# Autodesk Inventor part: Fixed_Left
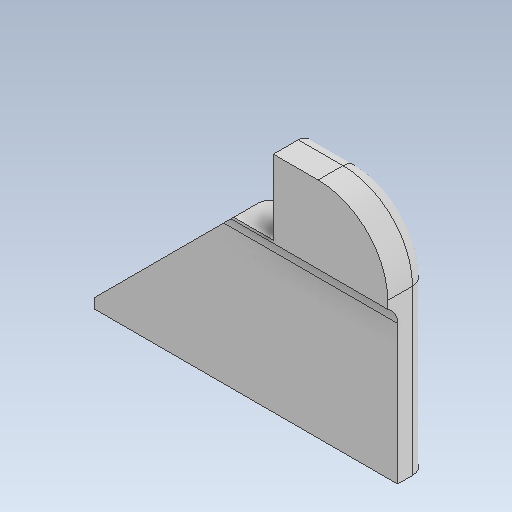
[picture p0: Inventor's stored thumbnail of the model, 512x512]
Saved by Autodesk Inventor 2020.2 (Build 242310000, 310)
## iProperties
Created: 2019-12
Part Number: Fixed_Left
Material: Generic
Document SubType Name: Modeling
Designer: Patrick Everitt
Density: 1 g/cm^3
Appearance: Default
Description: 1x6 CRS 8 Lg
Author: Patrick Everitt
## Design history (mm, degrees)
sketch "Sketch1"
  geometry: L1 (25.4, -50.8)-(25.4, -3.175); L2 (25.4, -50.8)-(73.025, -50.8); L3 (25.4, -3.175)-(53.975, -3.175); L4 (98.425, -47.625)-(98.425, -152.4); L5 (25.4, -50.8)-(0, -50.8); L6 (98.425, -152.4)-(-95.25, -152.4); L7 (0, -50.8)-(-95.25, -146.05); L8 (-95.25, -146.05)-(-95.25, -152.4); A1 r 44.45 centre (53.975, -47.625) between (98.425, -47.625) and (53.975, -3.175); 2 further points
  constraints: 16 end point, 4 perpendicular, 3 horizontal, 2 point on circle, 2 point on line, 2 tangent, 1 centre point, 1 vertical
  dimensions: "d6" = 47.625 distance of L1.start L1.end; "d7" = 90 deg angle of L2 L1 (derived); "d8" = 73.025 distance of L1.end point (98.425, -3.175); "d9" = 90 deg angle of L1 L3 (derived); "d11" = 90 deg angle of L3 L4 (derived); "d14" = 25.4 horizontal distance of point (0, 0) L1.end; "d17" = 101.6 vertical distance of L6.end L5.end; "d18" = 44.45 radius of A1 (derived); "d62" = 3.175 vertical distance of point (0, 0) L1.end; "d66" = 25.4 distance of L1.start L5.end (= d14); "d67" = 135 deg angle of L5 L7; "d69" = 6.35 distance of L7.end L6.end
extrude "Extrusion1" new body sketch "Sketch1" distance "d25" = 25.4; taper "d26" = 0 deg
sketch "Sketch2"
  geometry: L1 (0, 0)-(-25.4, 0) reference; L2 (-19.05, 0)-(-19.05, 88.9); L3 (-25.4, 101.6)-(-25.4, 0) reference; L4 (-31.75, 101.6)-(-44.45, 101.6); L5 (-44.45, 101.6)-(-44.45, 0); L6 (-44.45, 0)-(-19.05, 0); A1 r 12.7 centre (-31.75, 88.9) between (-19.05, 88.9) and (-31.75, 101.6); 4 further points
  constraints: 8 end point, 2 perpendicular, 2 point on circle, 2 point on line, 2 tangent, 1 centre point, 1 parallel
  dimensions: "d37" = 25.4 distance of point (-19.05, 101.6) L4.end; "d39" = 12.7 radius of A1 (derived); "d40" = 19.05 distance of L1.start L2.start; "d47" = 101.6 distance of L4.end L5.end; "d48" = 90 deg angle of L6 L3; "d49" = 101.6 distance between parallel lines of L1 L4
extrude "Extrusion3" cut sketch "Sketch2" extent not by distance; stored distance "d50" = 0; taper "d51" = 0 deg
sketch "Sketch4"
  geometry: L1 (193.675, 0)-(193.675, 19.05) reference; L2 (0, 0)-(0, 19.05) reference; L3 (0, 0)-(193.675, 0) reference; 3 further points
  dimensions: "d70" = 38.1 distance from line of L1 point (155.575, 9.525); "d71" = 38.1 distance from line of L2 point (38.1, 9.525) (= d70); "d74" = 9.525 distance from line of L3 point (38.1, 9.525); "d76" = 9.525 distance from line of L3 point (155.575, 9.525) (= d74)
hole "Hole1" sketch "Sketch4" at (38.1, 9.525), (155.575, 9.525) diameter "d77" = 7.7978; stored, may be unused: countersink angle "d81" = 82 deg, drill point angle "d83" = 118 deg; dims "d78" = 19.05, "d79" = 9.525, "d80" = 6.35, "d82" = 27.0002
fillet "Fillet1" dims "d84" = 9.525
body "Solid1"
